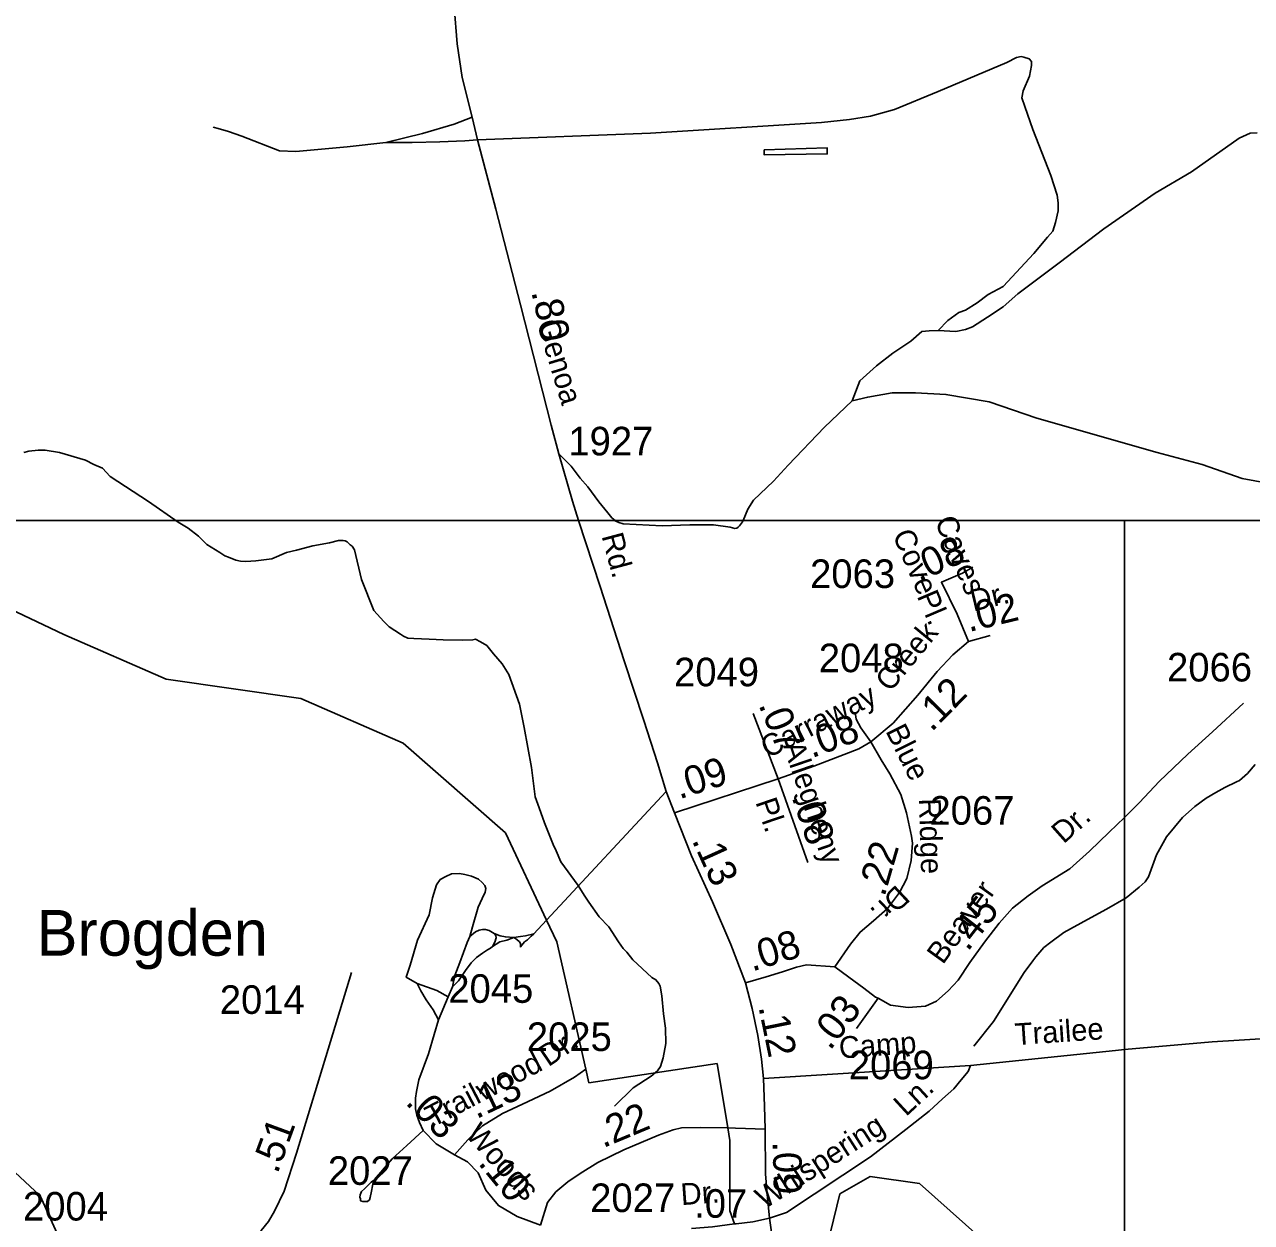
# Model space of a CAD drawing. Extents: x 2206922 to 2357709, y 510027 to 673830.
# Drawn here: x 2291479 to 2296847, y 563987 to 569227 of the extents above; entities that cross this region are included whole.
import ezdxf

# ---------------------------------------------------------------- set-up
doc = ezdxf.new("R2010")
doc.units = 0
for name, color, linetype in [('Exist Boundary Political Urban Extension UEB', 7, 'Continuous'), ('Exist Civil Demographics City Label', 7, 'Continuous'), ('Exist Hydrographic Creek Single Shore', 7, 'Continuous'), ('Exist Hydrographic Misc Water Feature', 7, 'Continuous'), ('Exist Hydrographic Pond Under 1500 Sq Ft', 7, 'Continuous'), ('Exist Road Non-System Type 51', 7, 'Continuous'), ('Exist Road Non-System Type 51 Label', 7, 'Continuous'), ('Exist Road Secondary Mileage Hundredths English Label', 7, 'Continuous'), ('Exist Road Secondary Type 51 Attributed', 7, 'Continuous'), ('Exist Road Secondary Type 51 Label', 7, 'Continuous'), ('Exist Road Secondary Type 51 Number Label', 7, 'Continuous'), ('Map Preparation Inset Cut Line', 7, 'Continuous')]:
    doc.layers.add(name, color=color, linetype=linetype)

msp = doc.modelspace()

# ---------------------------------------------------------------- linework, layer by layer
at = {"layer": 'Exist Boundary Political Urban Extension UEB'}
for points in [[(2293762.8, 565309.9), (2293583.6, 565690.7), (2293135.2, 566082.9), (2292686.8, 566279.1), (2292098.3, 566363.1), (2291649.9, 566559.3), (2291117.5, 566811.4), (2290809.2, 567016.9)], [(2293934.3, 564657.6), (2293807.8, 565214.3), (2293762.8, 565309.9)], [(2294555.3, 564400.3), (2294508.4, 564681.9), (2293947.9, 564597.9), (2293934.3, 564657.6)], [(2294584.8, 563980.4), (2294564.4, 564037.5), (2294564.4, 564345.7), (2294555.3, 564400.3)]]:
    msp.add_lwpolyline(points, dxfattribs=at)
at = {"layer": 'Exist Hydrographic Creek Single Shore'}
msp.add_lwpolyline([(2291136.9, 562540.9), (2291593, 562771.1), (2291741.8, 562915.6), (2291798, 563124.4), (2291820, 563497.8), (2291546.8, 564103.5), (2291193.9, 564432)], dxfattribs=at)
at = {"layer": 'Exist Hydrographic Misc Water Feature'}
for points in [[(2294714.7, 568678.8), (2294714.7, 568660.9), (2294714.9, 568656.8), (2294990.5, 568661.6), (2294990.7, 568687.5), (2294714.7, 568678.8)], [(2294060.4, 564495.1), (2294141.4, 564575.7), (2294220.7, 564626.6), (2294248.6, 564650.8), (2294260.5, 564668.9), (2294272, 564706.9), (2294283.7, 564769.2), (2294283.1, 564837), (2294274.7, 564899.1), (2294267.5, 564978.9), (2294259.1, 565020.7), (2294253.1, 565032.6), (2294240.8, 565048.5), (2294223, 565058.2), (2294140.1, 565135.5), (2294113.9, 565169.1), (2294097.7, 565184.9), (2294077.8, 565215), (2294034.9, 565280.3), (2293992.5, 565324), (2293947.8, 565387.5), (2293927.7, 565419.3), (2293901.5, 565461), (2293824.4, 565564.3), (2293804.3, 565611.9), (2293792, 565640.1), (2293753, 565735.6), (2293730.2, 565801), (2293712, 565849.2), (2293696.6, 565976.8), (2293665, 566152.3), (2293643.7, 566254), (2293597, 566383.6), (2293568.2, 566431.3), (2293530.1, 566475.1), (2293501.6, 566510.7), (2293473.5, 566526.7), (2293451.4, 566538.1), (2293439.5, 566536.2), (2293395.8, 566533.9), (2293309.7, 566535.1), (2293249.4, 566538.5), (2293181.5, 566541.8), (2293155.5, 566543.3), (2293137.2, 566551.4), (2293123.7, 566561.1), (2293073.3, 566592.6), (2293050.7, 566616.3), (2293006.4, 566663.9), (2292953.3, 566799.3), (2292922.1, 566928.8), (2292912.1, 566945), (2292903.7, 566951.1), (2292889.7, 566964.6), (2292881.5, 566968.6), (2292871.7, 566970.5), (2292851.6, 566970.3), (2292812.2, 566960), (2292739.8, 566947.4), (2292668.3, 566928.6), (2292624.6, 566918.1), (2292560.6, 566889.6), (2292490.9, 566881), (2292447, 566878.7), (2292423.2, 566880.3), (2292402.9, 566884.2), (2292370.7, 566897.9), (2292354.7, 566903.6), (2292332.4, 566917.5), (2292276.2, 566952.7), (2292240.1, 566988.6), (2292193.8, 567024), (2292151.3, 567049.8), (2292020.5, 567140.4), (2291853.6, 567250.8), (2291819.2, 567286.4), (2291781.4, 567302.2), (2291745.1, 567321.9), (2291630.9, 567354.9), (2291568.4, 567365.9), (2291538.6, 567365.9), (2291497.2, 567361.2), (2291474.9, 567355.2)], [(2295631.3, 564757.7), (2295718.2, 564866.7), (2295851.9, 565079.7), (2295889.4, 565132), (2295903.2, 565148.2), (2295938.6, 565190.3), (2295968.4, 565212.6), (2296026, 565255), (2296129.3, 565312), (2296213, 565357), (2296298.7, 565407.7), (2296355.7, 565454.3), (2296381.6, 565476.4), (2296395.5, 565498.6), (2296430.6, 565594.7), (2296474.2, 565673.3), (2296544.8, 565758), (2296598.3, 565806.3), (2296648.1, 565842.6), (2296690.2, 565867.1), (2296729.5, 565889.5), (2296781.2, 565914.2), (2296793.7, 565920), (2296829, 565950.4), (2296862.8, 565990.7)]]:
    msp.add_lwpolyline(points, dxfattribs=at)
at = {"layer": 'Exist Hydrographic Pond Under 1500 Sq Ft'}
msp.add_lwpolyline([(2295501.1, 563466.1), (2295291.9, 563529.4), (2295055.9, 563803), (2295005, 563945.1), (2295045, 564111.5), (2295177.9, 564187.5), (2295394, 564156.9), (2295663.1, 563918.7), (2295748, 563710.3), (2295741, 563608.8), (2295566.9, 563484.4), (2295501.1, 563466.1)], dxfattribs=at)
at = {"layer": 'Exist Road Non-System Type 51'}
for p, q in [((2293762.8, 565309.9), (2294285.4, 565872.5)), ((2293707.1, 565250), (2293762.8, 565309.9)), ((2293332.3, 564973.6), (2293350.4, 565017.3)), ((2293332.3, 564973.6), (2293290.2, 564872.7)), ((2294711.1, 564616.2), (2295617.7, 564673.2))]:
    msp.add_line(p, q, dxfattribs=at)
for points in [[(2293460.8, 568723.2), (2294217.8, 568752.1), (2294965.1, 568798.8), (2295087.4, 568812.1), (2295179.3, 568827.1), (2295284.8, 568856.1), (2295476.1, 568933.8), (2295776.8, 569060.5), (2295818.4, 569082.8), (2295838.5, 569087), (2295850.4, 569085.2), (2295874.5, 569077.5), (2295884.6, 569065.5), (2295884.7, 569047.5), (2295875.1, 569001.5), (2295847.8, 568937.3), (2295842, 568907.2), (2295854.5, 568869.4), (2295889.4, 568767.7), (2295969.3, 568566.6), (2295996, 568480.9), (2296000.3, 568447), (2296000.6, 568413), (2295989.1, 568360.9), (2295977.6, 568322.9), (2295953.8, 568296.6), (2295894.4, 568226), (2295760.1, 568080.8), (2295694, 568046.7), (2295646.2, 568010.2), (2295596.1, 567978.3), (2295566.5, 567966.9), (2295518.6, 567932.7), (2295475.3, 567889.4)], [(2293059.8, 568711.1), (2293219.3, 568750.6), (2293359, 568791.6), (2293436.5, 568822)], [(2292303.5, 568778.7), (2292326.3, 568772.6), (2292370.3, 568758.9), (2292429.6, 568738.4), (2292593.6, 568675.4), (2292665, 568672.3), (2292889.7, 568692.1), (2293059.8, 568711.1)], [(2296870.9, 568753.1), (2296840.9, 568752.7), (2296793.3, 568730.3), (2296584.8, 568583.4), (2296425.3, 568490), (2296201.3, 568333), (2296004.8, 568185.2), (2295824.1, 568049.5), (2295760.1, 567991.9), (2295691.8, 567946.4), (2295625.7, 567905.3), (2295596.1, 567893.9), (2295552.8, 567884.8), (2295475.3, 567889.4)], [(2293059.8, 568711.1), (2293175.2, 568711.1), (2293295.2, 568714.1), (2293404.6, 568718.7), (2293460.8, 568723.2)], [(2295475.3, 567889.4), (2295436.6, 567887.1), (2295404.7, 567884.8), (2295356.9, 567841.5), (2295277.2, 567789.1), (2295206.5, 567734.4), (2295133.6, 567668.3), (2295099.5, 567581.7)], [(2295099.5, 567581.7), (2295167.8, 567597.6), (2295274.9, 567615.9), (2295377.4, 567615.9), (2295509.5, 567609), (2295698.6, 567577.1), (2295908.2, 567505.3), (2296434.4, 567354.9), (2296630.3, 567302.4), (2296805.7, 567240.9), (2296917.4, 567220.4)], [(2295099.5, 567581.7), (2294978.7, 567466.5), (2294819.3, 567300.2), (2294755.5, 567229.5), (2294667.3, 567147.3), (2294643.7, 567107), (2294622, 567057.4)], [(2294062.5, 567057.4), (2294048.3, 567069.8), (2294030.2, 567090.8), (2293991.1, 567139), (2293942.9, 567205.3), (2293909.8, 567243.4), (2293869.7, 567294.7), (2293815.5, 567348.9)], [(2294622, 567057.4), (2294619.4, 567051.5), (2294606.4, 567034.1), (2294600.6, 567028.3), (2294594.8, 567024.7), (2294586.3, 567023.3), (2294566.4, 567027.8), (2294493.5, 567039.2), (2294388.7, 567039.2), (2294268, 567034.6), (2294097.1, 567043.7), (2294078.9, 567048.3), (2294063.3, 567056.7), (2294062.5, 567057.4)], [(2295181.5, 566089), (2295137.4, 566150.6), (2295117.7, 566188.6), (2295113.1, 566219)], [(2293427.1, 565237.2), (2293439.2, 565280.8), (2293463.3, 565366.7), (2293481.3, 565404.3), (2293493.4, 565431.4), (2293496.4, 565448), (2293491.8, 565460.9), (2293481.5, 565474.2), (2293464.8, 565488.7), (2293434.7, 565502.2), (2293404.6, 565509.8), (2293382, 565512.8), (2293345.9, 565511.3), (2293321.8, 565500.7), (2293297.7, 565487.2), (2293281.1, 565464.6), (2293263.1, 565407.3), (2293249.5, 565332), (2293198.3, 565222.1), (2293165.2, 565112.2), (2293148.7, 565059.4), (2293196.8, 565032.3)], [(2293427.1, 565237.2), (2293451.2, 565258.2), (2293467.8, 565265.8), (2293482.8, 565268.8), (2293494.9, 565268.8), (2293511.4, 565264.3), (2293526.5, 565255.2), (2293534, 565250.7)], [(2293534, 565250.7), (2293540, 565241.7), (2293541.5, 565232.6), (2293535.5, 565213.1), (2293531, 565202.5), (2293526.5, 565193.5)], [(2293619.8, 565234.1), (2293582.2, 565236.4), (2293559.6, 565240.9), (2293534, 565250.7)], [(2293707.1, 565250), (2293671, 565240.9), (2293648.4, 565237.9), (2293619.8, 565234.1)], [(2293619.8, 565234.1), (2293631.8, 565225.1), (2293643.9, 565214.6), (2293648.4, 565207), (2293648.4, 565192), (2293666.5, 565214.6), (2293679.6, 565224), (2293694.7, 565239), (2293707.1, 565250)], [(2293350.4, 565017.3), (2293360.9, 565067), (2293383.5, 565124.2), (2293415.1, 565211.6), (2293427.1, 565237.2)], [(2293350.4, 565017.3), (2293377.5, 565044.4), (2293407.6, 565089.6), (2293433.2, 565122.7), (2293455.7, 565145.3), (2293482.8, 565164.9), (2293503.9, 565179.9), (2293517.4, 565187.5), (2293526.5, 565193.5)], [(2293526.5, 565193.5), (2293558.1, 565214.6), (2293588.2, 565222.1), (2293619.8, 565234.1)], [(2293196.8, 565032.3), (2293282.6, 565002.2), (2293332.3, 564973.6)], [(2293290.2, 564872.7), (2293266.1, 564916.4), (2293236, 564960.1), (2293211.9, 565000.7), (2293196.8, 565032.3)], [(2293222.1, 564389.5), (2293205.9, 564423.9), (2293195.3, 564457), (2293189.3, 564484.1), (2293189.3, 564506.7), (2293189.3, 564530.8), (2293193.8, 564559.4), (2293204.4, 564610.7), (2293246.5, 564725.1), (2293270.6, 564809.4), (2293290.2, 564872.7)], [(2296290.5, 564742.9), (2296674.4, 564777.4), (2296934.2, 564793.7)], [(2295617.7, 564673.2), (2296251, 564739.4), (2296290.5, 564742.9)], [(2294738.4, 564005.3), (2294812.8, 564031.2), (2295180.3, 564274.3), (2295334.8, 564393), (2295436, 564473.7), (2295495.4, 564528.3), (2295545.1, 564570.9), (2295576.7, 564611), (2295607.1, 564647.3), (2295617.7, 564673.2)], [(2293222.1, 564389.5), (2293151.7, 564323), (2293087, 564265.8), (2293028.3, 564196.5), (2293005.7, 564170.9)], [(2293005.7, 564170.9), (2292996.7, 564124.2), (2292990.6, 564095.6), (2292987.6, 564086.6), (2292978.6, 564079), (2292972.6, 564079), (2292968.1, 564079), (2292959, 564079), (2292948.5, 564082), (2292948.5, 564089.6), (2292945.5, 564097.1), (2292947, 564107.6), (2292953, 564122.7), (2292966.6, 564134.7), (2292995.1, 564163.4), (2293005.7, 564170.9)]]:
    msp.add_lwpolyline(points, dxfattribs=at)
at = {"layer": 'Exist Road Secondary Type 51 Attributed'}
for p, q in [((2294666.6, 566213.7), (2294776, 565927)), ((2294321.9, 565778.3), (2294776, 565927)), ((2294776, 565927), (2294905.1, 565561.8)), ((2295212.7, 564967.7), (2295119.2, 564835.4))]:
    msp.add_line(p, q, dxfattribs=at)
for points in [[(2294321.9, 565778.3), (2294285.4, 565872.5), (2294247.5, 565997.1), (2294188.2, 566182.5), (2294101.7, 566443.9), (2293996.9, 566768.3), (2293903, 567057.4), (2293875.7, 567141.5), (2293815.5, 567348.9), (2293782.7, 567474.9), (2293649.1, 568001.4), (2293541.3, 568419.3), (2293460.8, 568723.2), (2293436.5, 568822), (2293393.9, 568995.2), (2293371.2, 569143.4), (2293359, 569306), (2293360.5, 569411.6), (2293372.7, 569575), (2293384.8, 569701.1)], [(2295608.2, 566529), (2295559.6, 566647.5), (2295489.8, 566787.3), (2295582.4, 566827.6), (2295628, 566853.4)], [(2295608.2, 566529), (2295703.9, 566554.8)], [(2295181.5, 566089), (2295278.7, 566171.1), (2295386.5, 566294.2), (2295471.6, 566396.8), (2295539.9, 566469.7), (2295608.2, 566529)], [(2295212.7, 564967.7), (2295268, 564937.2), (2295344, 564926.6), (2295419.9, 564932.6), (2295468.5, 564955.4), (2295520.1, 564999.5), (2295563, 565046.2), (2295614.5, 565124.8), (2295678.4, 565213.5), (2295742.4, 565295.8), (2295800.6, 565361.8), (2295869.7, 565416.2), (2295930.6, 565459.4), (2296051.7, 565534.2), (2296138, 565611), (2296224.2, 565694.1), (2296290.5, 565759), (2296356.4, 565823.6), (2296442.3, 565916.3), (2296568.5, 566036.1), (2296676.3, 566132.8), (2296811.8, 566259.3)], [(2294776, 565927), (2294931.2, 565983.5), (2295065.3, 566033.3), (2295129.5, 566058.5), (2295181.5, 566089)], [(2295023.9, 565105.8), (2295091.9, 565203.9), (2295134.4, 565257.1), (2295193.6, 565305.7), (2295254.4, 565360.4), (2295306, 565430.3), (2295338.5, 565491.4), (2295357.6, 565570.9), (2295363.7, 565646.8), (2295359.2, 565677.2), (2295337.9, 565779.1), (2295312.1, 565858.8), (2295265, 565949.2), (2295227, 566010), (2295181.5, 566089)], [(2294633.2, 565034.5), (2294569.4, 565202.4), (2294488.9, 565389.3), (2294396.3, 565591.4), (2294321.9, 565778.3)], [(2294633.2, 565034.5), (2294722.8, 565061.8), (2294794.2, 565083.1), (2294856.5, 565104.4), (2294900.5, 565113.5), (2295023.9, 565105.8)], [(2295023.9, 565105.8), (2295085.3, 565060.2), (2295151.1, 565011.7), (2295201.6, 564971.9), (2295212.7, 564967.7)], [(2292909.4, 565080.5), (2292668.5, 564289.9), (2292614.3, 564123.4), (2292572.2, 564036.1), (2292546.6, 563990.9), (2292513.5, 563951.8), (2292483.4, 563921.6), (2292454.8, 563900.6), (2292384, 563861.4), (2292260.6, 563805.7), (2291642, 563493.9)], [(2294718.3, 564395), (2294715.6, 564496.1), (2294711.1, 564616.2), (2294703.5, 564701.3), (2294686.8, 564804.6), (2294662.5, 564923.1), (2294633.2, 565034.5)], [(2293359.8, 564283.1), (2293418, 564349.1), (2293482.6, 564409.1), (2293569.6, 564463.5), (2293656.9, 564505.1), (2293778.6, 564560.8), (2293885.5, 564622.5), (2293934.3, 564657.6)], [(2293359.8, 564283.1), (2293279.4, 564331.1), (2293222.1, 564389.5)], [(2293735.3, 563974.6), (2293767.2, 564074.8), (2293803.8, 564120.9), (2293856.3, 564164.4), (2293909, 564201.5), (2293986.7, 564249.2), (2294100.4, 564304.8), (2294252.9, 564368.4), (2294316.4, 564391.7), (2294352.2, 564400.3), (2294435, 564402.3), (2294555.3, 564400.3), (2294589.3, 564399.7), (2294718.3, 564395)], [(2294738.4, 564005.3), (2294733.8, 564050.9), (2294727.8, 564110.2), (2294720.2, 564199.8), (2294718.3, 564395)], [(2293735.3, 563974.6), (2293634.5, 564012.4), (2293551.9, 564061.1), (2293497, 564128.5), (2293463.2, 564203.9), (2293416.4, 564251.8), (2293359.8, 564283.1)], [(2294738.4, 564005.3), (2294664.3, 563990.4), (2294591.8, 563981.3), (2294584.8, 563980.4), (2294487.9, 563967.8), (2294396.4, 563961.2)], [(2295016.4, 563176.3), (2294955.3, 563345.1), (2294821.3, 563689.1), (2294762.7, 563870.1), (2294746.3, 563944.6), (2294738.4, 564005.3)]]:
    msp.add_lwpolyline(points, dxfattribs=at)
at = {"layer": 'Map Preparation Inset Cut Line'}
for p, q in [((2290820.2, 567057.4), (2293903, 567057.4)), ((2293903, 567057.4), (2294062.5, 567057.4)), ((2294062.5, 567057.4), (2294622, 567057.4)), ((2294622, 567057.4), (2296290.5, 567057.4)), ((2301953, 567057.4), (2296290.5, 567057.4)), ((2296290.5, 567057.4), (2296290.5, 565759)), ((2296290.5, 565759), (2296290.5, 564742.9)), ((2296290.5, 564742.9), (2296290.5, 562498.7))]:
    msp.add_line(p, q, dxfattribs=at)

# ---------------------------------------------------------------- texts
at = {"layer": 'Exist Civil Demographics City Label'}
msp.add_text('Brogden', height=200, dxfattribs=at).set_placement((2291531.9, 565153.9))
at = {"layer": 'Exist Road Non-System Type 51 Label'}
for s, rotation, p in [('Trailee', 3.874, (2295814.5, 564762.4)), ('Camp', 4.1963, (2295045.2, 564703.9)), ('Ln.', 42.589, (2295335, 564447.7)), ('Whispering', 32.6593, (2294716, 564043.3))]:
    msp.add_text(s, height=95, rotation=rotation, dxfattribs=at).set_placement(p)
at = {"layer": 'Exist Road Secondary Mileage Hundredths English Label'}
for s, rotation, p in [('.80', 282.9026, (2293695.2, 568057.9)), ('.08', 24.3938, (2295392.3, 566787)), ('.02', 13.5609, (2295610.2, 566569.2)), ('.12', 45.4849, (2295446.9, 566129.9)), ('.07', 292.5463, (2294688.6, 566251.6)), ('.08', 20.3881, (2294922.9, 566017.1)), ('.09', 17.9141, (2294343.2, 565837.3)), ('.08', 288.6342, (2294834.1, 565848.6)), ('.13', 294.3655, (2294397, 565658.9)), ('.22', 73.7236, (2295240.8, 565408.1)), ('.45', 52.1068, (2295605.2, 565168.6)), ('.08', 17.0121, (2294661.7, 565084.1)), ('.03', 52.1298, (2295002.7, 564735.7)), ('.12', 281.5925, (2294689.2, 564929.8)), ('.13', 25.4861, (2293455.4, 564437.8)), ('.03', 314.4655, (2293140.8, 564508)), ('.22', 22.6324, (2294009.6, 564311.4)), ('.51', 69.8491, (2292585.2, 564196.4)), ('.09', 271.4117, (2294751.7, 564340.6)), ('.10', 309.202, (2293459.8, 564245.4)), ('.07', 359.9156, (2294408, 564007.7))]:
    msp.add_text(s, height=125, rotation=rotation, dxfattribs=at).set_placement(p)
at = {"layer": 'Exist Road Secondary Type 51 Label'}
for s, rotation, p in [('Genoa', 286.9532, (2293718.9, 567921.7)), ('Caves', 293.0602, (2295459.4, 567054.8)), ('Rd.', 285.0341, (2294002.5, 566990.2)), ('Cove', 293.0602, (2295274.7, 566996)), ('Pl.', 293.0602, (2295381.4, 566727.5)), ('Dr.', 13.5609, (2295629.8, 566659.1)), ('Creek', 50.6208, (2295266.3, 566303.4)), ('Carraway', 26.9127, (2294730.3, 566015.8)), ('Blue', 296.6218, (2295243.8, 566137.2)), ('Allegheny', 288.7595, (2294795.7, 566073.6)), ('Pl.', 288.7595, (2294675.4, 565826.1)), ('Ridge', 271.637, (2295391.9, 565841.4)), ('Dr.', 41.6322, (2296024.5, 565640.5)), ('Beaver', 54.2383, (2295496.5, 565111.5)), ('Dr.', 223.2968, (2295294.3, 565468.2)), ('Dr.', 34.2428, (2293770.7, 564665.5)), ('Trailwood', 27.533, (2293264.2, 564401.5)), ('Woods', 311.9966, (2293403.8, 564368.2)), ('Dr.', 4.154, (2294352.7, 564062.5))]:
    msp.add_text(s, height=95, rotation=rotation, dxfattribs=at).set_placement(p)
at = {"layer": 'Exist Road Secondary Type 51 Number Label'}
for s, p in [('1927', (2293857.9, 567342.5)), ('2063', (2294915.5, 566762.4)), ('2048', (2294953.5, 566394)), ('2049', (2294320.3, 566332.4)), ('2066', (2296477.2, 566353.5)), ('2067', (2295437.8, 565726.9)), ('2045', (2293332.6, 564947.7)), ('2014', (2292332.9, 564899.2)), ('2025', (2293676.1, 564737)), ('2069', (2295084.9, 564613.3)), ('2027', (2292805.7, 564151.4)), ('2004', (2291471.8, 563995.3)), ('2027', (2293953.4, 564032.4))]:
    msp.add_text(s, height=125, dxfattribs=at).set_placement(p)

doc.saveas('drawing.dxf')
